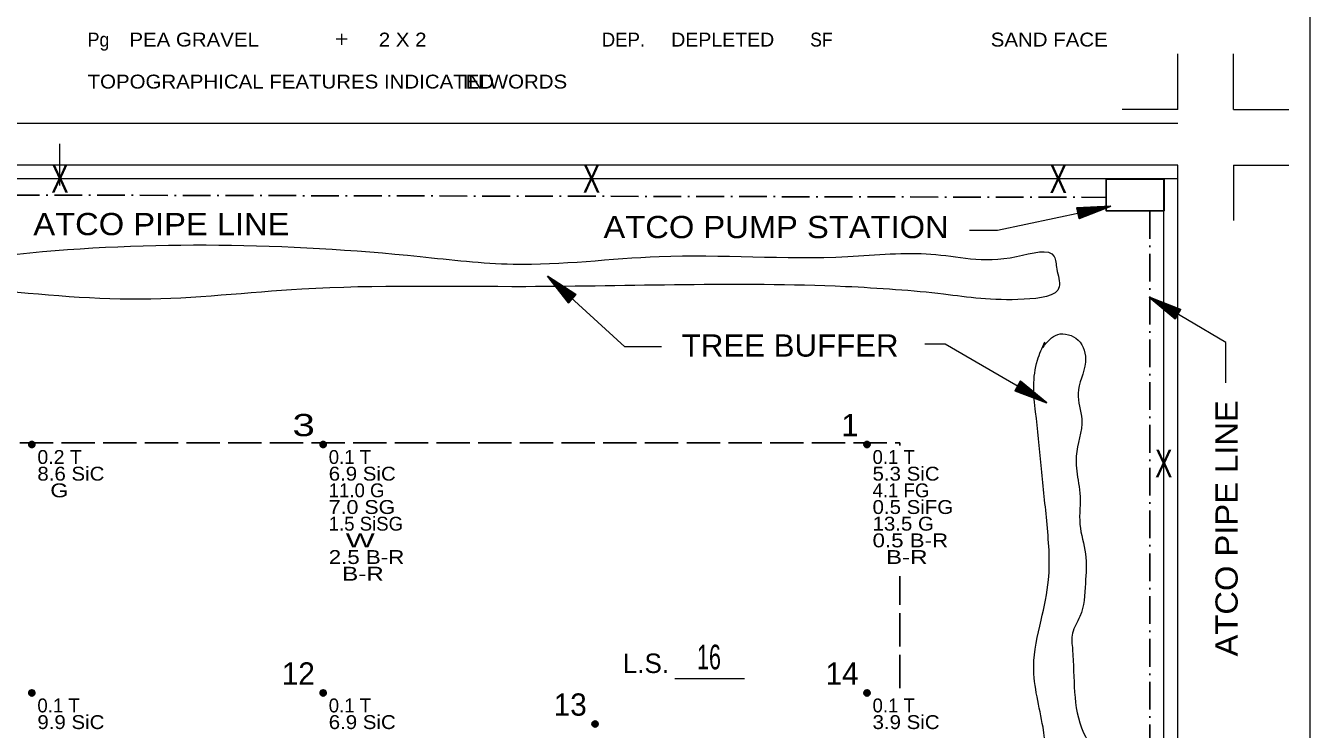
# Model space of a CAD drawing. Extents: x -496 to 480, y -450 to 700.
# Drawn here: x -12.3 to 450, y 199.3 to 452.5 of the extents above; entities that cross this region are included whole.
import ezdxf
from ezdxf.enums import TextEntityAlignment as Align

# ---------------------------------------------------------------- set-up
doc = ezdxf.new("R2010")
doc.units = 0
doc.header["$LTSCALE"] = 2
doc.linetypes.add('DOT_DASHED', pattern=[7.7, 5, -1.2, 0.3, -1.2])
doc.linetypes.add('LONG_DASHED', pattern=[7.5, 6, -1.5])
for name, color, linetype, lineweight in [('1', 7, 'Continuous', 13), ('2', 7, 'Continuous', 35), ('3', 7, 'Continuous', 13), ('4', 7, 'Continuous', 25)]:
    doc.layers.add(name, color=color, linetype=linetype, lineweight=lineweight)

msp = doc.modelspace()

# ---------------------------------------------------------------- linework, layer by layer
at = {"layer": '1'}
for p, q in [((101.291, 449.597), (101.291, 445.597)), ((103.353, 447.618), (99.353, 447.618)), ((402.281, 422.339), (402.281, 442.339)), ((422.281, 422.339), (422.281, 442.339)), ((402.281, 422.339), (382.281, 422.339)), ((422.281, 422.339), (442.281, 422.339)), ((-0.017, 394.973), (-0.017, 409.973)), ((402.281, 402.339), (-402.391, 402.339)), ((402.281, -245.555), (402.281, 402.339)), ((422.281, 402.339), (442.281, 402.339)), ((422.281, 402.339), (422.281, 382.339)), ((221.34, 217.545), (246.34, 217.545))]:
    msp.add_line(p, q, dxfattribs=at)
msp.add_lwpolyline([(449.983, -450.027), (449.983, 399.973), (449.983, 699.973), (-450.017, 699.973), (-450.017, 49.973), (-450.017, -450.027)], dxfattribs=at)
at = {"layer": '2', "linetype": 'LONG_DASHED', "lineweight": 25}
for p, q in [((-74.459, 302.339), (302.281, 302.339)), ((302.281, 301.455), (302.281, 302.339)), ((302.281, 214.038), (302.281, 254.384))]:
    msp.add_line(p, q, dxfattribs=at)
at = {"layer": '2'}
for centre in [(-10.129, 301.764), (94.721, 301.764), (290.441, 301.764), (-10.129, 212.364), (94.721, 212.364), (94.721, 212.364), (290.441, 212.364), (192.581, 201.189)]:
    msp.add_circle(centre, 1, dxfattribs=at)
for points in [[(-10.14, 302.651), (-9.409, 302.247), (-9.258, 301.398), (-9.943, 300.87), (-10.752, 301.101), (-11.038, 301.859), (-10.791, 302.421), (-10.218, 302.589), (-9.544, 302.095), (-9.561, 301.353), (-10.078, 301.095), (-10.6, 301.264), (-10.825, 301.91), (-10.241, 302.376), (-9.803, 301.842), (-9.842, 301.359), (-10.471, 301.494), (-10.325, 302.129), (-10.033, 301.578)], [(94.71, 302.651), (95.441, 302.247), (95.592, 301.398), (94.907, 300.87), (94.098, 301.101), (93.812, 301.859), (94.059, 302.421), (94.632, 302.589), (95.306, 302.095), (95.289, 301.353), (94.772, 301.095), (94.25, 301.264), (94.025, 301.91), (94.609, 302.376), (95.047, 301.842), (95.008, 301.359), (94.379, 301.494), (94.525, 302.129), (94.817, 301.578)], [(290.43, 302.651), (291.161, 302.247), (291.312, 301.398), (290.627, 300.87), (289.818, 301.101), (289.532, 301.859), (289.779, 302.421), (290.352, 302.589), (291.026, 302.095), (291.009, 301.353), (290.492, 301.095), (289.97, 301.264), (289.745, 301.91), (290.329, 302.376), (290.767, 301.842), (290.728, 301.359), (290.099, 301.494), (290.245, 302.129), (290.537, 301.578)], [(-10.14, 213.251), (-9.409, 212.847), (-9.258, 211.998), (-9.943, 211.47), (-10.752, 211.701), (-11.038, 212.459), (-10.791, 213.021), (-10.218, 213.189), (-9.544, 212.695), (-9.561, 211.953), (-10.078, 211.695), (-10.6, 211.864), (-10.825, 212.51), (-10.241, 212.976), (-9.803, 212.442), (-9.842, 211.959), (-10.471, 212.094), (-10.325, 212.729), (-10.033, 212.178)], [(94.71, 213.251), (95.441, 212.847), (95.592, 211.998), (94.907, 211.47), (94.098, 211.701), (93.812, 212.459), (94.059, 213.021), (94.632, 213.189), (95.306, 212.695), (95.289, 211.953), (94.772, 211.695), (94.25, 211.864), (94.025, 212.51), (94.609, 212.976), (95.047, 212.442), (95.008, 211.959), (94.379, 212.094), (94.525, 212.729), (94.817, 212.178)], [(94.71, 213.251), (95.441, 212.847), (95.592, 211.998), (94.907, 211.47), (94.098, 211.701), (93.812, 212.459), (94.059, 213.021), (94.632, 213.189), (95.306, 212.695), (95.289, 211.953), (94.772, 211.695), (94.25, 211.864), (94.025, 212.51), (94.609, 212.976), (95.047, 212.442), (95.008, 211.959), (94.379, 212.094), (94.525, 212.729), (94.817, 212.178)], [(290.43, 213.251), (291.161, 212.847), (291.312, 211.998), (290.627, 211.47), (289.818, 211.701), (289.532, 212.459), (289.779, 213.021), (290.352, 213.189), (291.026, 212.695), (291.009, 211.953), (290.492, 211.695), (289.97, 211.864), (289.745, 212.51), (290.329, 212.976), (290.767, 212.442), (290.728, 211.959), (290.099, 212.094), (290.245, 212.729), (290.537, 212.178)], [(192.57, 202.076), (193.301, 201.672), (193.452, 200.823), (192.767, 200.295), (191.958, 200.526), (191.672, 201.284), (191.919, 201.846), (192.492, 202.014), (193.166, 201.52), (193.149, 200.778), (192.632, 200.52), (192.11, 200.689), (191.885, 201.335), (192.469, 201.801), (192.907, 201.267), (192.868, 200.784), (192.239, 200.919), (192.385, 201.554), (192.677, 201.003)]]:
    msp.add_spline(points, degree=3, dxfattribs=at)
at = {"layer": '3'}
for p, q in [((402.281, 417.339), (-402.391, 417.339)), ((402.281, 397.339), (-402.391, 397.339)), ((397.281, -246.457), (397.281, 397.339))]:
    msp.add_line(p, q, dxfattribs=at)
at = {"layer": '3', "linetype": 'DOT_DASHED', "lineweight": 25}
for p, q in [((-402.402, 392.339), (376.548, 390.701)), ((392.281, 385.802), (392.281, -246.006))]:
    msp.add_line(p, q, dxfattribs=at)
at = {"layer": '3', "lineweight": 25}
msp.add_lwpolyline([(376.548, 397.28), (397.376, 397.28), (397.376, 385.802), (376.548, 385.802)], close=True, dxfattribs=at)
at = {"layer": '3'}
for points in [[(-407.583, 368.504), (-377.691, 369.409), (-355.045, 369.409), (-344.175, 368.504), (-328.776, 371.218), (-313.377, 372.123), (-278.956, 368.504), (-253.593, 366.695), (-220.983, 368.504), (-195.62, 369.409), (-113.189, 371.218), (-62.463, 366.695), (-15.36, 370.314), (129.573, 369.409), (163.088, 366.695), (215.626, 369.409), (283.563, 369.409), (313.456, 370.314), (344.254, 369.409), (357.841, 369.409), (358.747, 364.885), (359.653, 358.552), (346.971, 354.028), (317.985, 355.837), (282.658, 358.552), (167.617, 358.552), (86.999, 357.647), (29.026, 354.028), (-29.853, 357.647), (-94.167, 358.552), (-118.624, 356.742), (-177.503, 359.456), (-248.158, 354.932), (-325.153, 358.552), (-355.951, 354.932), (-383.126, 358.552), (-389.467, 354.932), (-393.996, 342.265), (-393.09, 244.549), (-392.184, 178.5), (-393.996, 113.356), (-393.996, 88.927), (-393.09, 59.974), (-392.184, 33.736), (-397.619, 15.64), (-404.866, 15.64), (-411.207, 31.021), (-407.583, 90.737), (-410.301, 145.024), (-408.489, 188.453), (-408.489, 262.645), (-411.207, 278.931), (-407.583, 312.408), (-409.395, 347.694), (-409.395, 353.123), (-415.736, 357.647)], [(353.782, 336.707), (359.096, 341.351), (366.402, 339.361), (369.059, 331.4), (366.402, 320.121), (367.731, 310.833), (365.738, 297.564), (366.402, 288.94), (367.066, 284.296), (367.066, 273.017), (369.059, 262.402), (369.059, 251.787), (367.066, 239.846), (364.41, 233.875), (364.41, 227.904), (368.395, 198.049), (373.044, 186.771), (371.052, 177.483), (364.41, 148.955), (366.402, 133.696), (368.395, 121.091), (368.395, 112.466), (367.066, 99.861), (367.066, 72.66), (369.723, 64.699), (369.723, 49.44), (369.059, 40.815), (364.41, 24.893), (366.402, 3.663), (367.066, -2.971), (369.059, -10.932), (370.387, -17.567), (370.387, -25.528), (367.731, -28.845), (363.745, -29.509), (359.096, -25.528), (353.782, -9.606), (353.782, 1.673), (354.447, 22.239), (357.103, 35.508), (356.439, 57.401), (353.118, 69.343), (353.118, 100.524), (353.118, 123.081), (351.79, 140.331), (355.775, 152.272), (355.111, 170.185), (355.111, 184.117), (353.782, 200.04), (350.461, 221.933), (353.118, 238.519), (355.775, 253.114), (355.111, 274.344), (353.118, 294.247), (351.125, 313.487), (350.461, 322.775), (351.79, 332.063), (354.447, 338.697)]]:
    msp.add_spline(points, degree=3, dxfattribs=at)
at = {"layer": '4', "lineweight": 13}
for p, q in [((337.44, 378.889), (378.151, 387.481)), ((327.385, 378.889), (337.44, 378.889))]:
    msp.add_line(p, q, dxfattribs=at)
at = {"layer": '4'}
for points in [[(378.151, 387.481), (365.997, 386.96), (366.823, 383.046)], [(175.463, 362.311), (182.973, 352.74), (185.671, 355.693)], [(391.967, 354.757), (401.291, 346.942), (403.321, 350.388)], [(355.111, 316.804), (345.741, 324.563), (343.731, 321.104)]]:
    msp.add_lwpolyline(points, close=True, dxfattribs=at)
for points in [[(366.117, 386.865), (377.589, 387.363), (366.948, 383.241), (366.196, 386.704), (376.869, 387.211), (367.103, 383.448), (366.394, 386.592), (376.107, 387.051), (367.248, 383.702), (366.566, 386.408), (375.237, 386.888), (367.442, 383.941), (366.824, 386.24), (374.194, 386.692), (367.579, 384.235), (367.088, 386.03), (373.071, 386.476), (367.786, 384.611), (367.391, 385.853), (371.829, 386.28), (368.07, 384.936), (367.762, 385.666), (370.374, 385.952), (368.375, 385.374)], [(182.981, 352.893), (175.886, 361.923), (185.44, 355.681), (183.065, 353.051), (176.43, 361.426), (185.181, 355.686), (183.041, 353.278), (177.005, 360.901), (184.891, 355.656), (183.09, 353.524), (177.644, 360.289), (184.583, 355.674), (183.076, 353.832), (178.411, 359.556), (184.264, 355.614), (183.092, 354.169), (179.242, 358.769), (183.839, 355.563), (183.06, 354.518), (180.125, 357.874), (183.409, 355.604), (182.996, 354.928), (181.24, 356.884), (182.875, 355.597)], [(401.266, 347.094), (392.461, 354.465), (403.098, 350.329), (401.317, 347.266), (393.096, 354.091), (402.843, 350.281), (401.246, 347.482), (393.766, 353.696), (402.565, 350.192), (401.243, 347.734), (394.518, 353.229), (402.26, 350.145), (401.166, 348.032), (395.42, 352.67), (401.961, 350.021), (401.112, 348.365), (396.395, 352.072), (401.555, 349.883), (401.009, 348.7), (397.444, 351.378), (401.126, 349.835), (400.861, 349.088), (398.74, 350.639), (400.605, 349.717)], [(345.766, 324.411), (354.615, 317.093), (343.954, 321.164), (345.716, 324.239), (353.978, 317.463), (344.208, 321.215), (345.789, 324.023), (353.305, 317.854), (344.486, 321.306), (345.793, 323.771), (352.551, 318.317), (344.79, 321.354), (345.872, 323.473), (351.645, 318.87), (345.089, 321.48), (345.928, 323.141), (350.667, 319.463), (345.494, 321.62), (346.033, 322.806), (349.614, 320.15), (345.922, 321.671), (346.183, 322.419), (348.314, 320.881), (346.443, 321.792)]]:
    msp.add_lwpolyline(points, dxfattribs=at)
at = {"layer": '4', "lineweight": 13}
for points in [[(216.467, 336.875), (203.302, 336.875), (175.463, 362.311)], [(419.592, 323.988), (419.592, 338.479), (391.967, 354.757)], [(311.273, 338.034), (318.58, 338.034), (355.111, 316.804)]]:
    msp.add_lwpolyline(points, dxfattribs=at)

# ---------------------------------------------------------------- texts
at = {"layer": '1'}
for s, width, p in [('Pg', 0.95, (9.983, 444.973)), ('PEA GRAVEL', 1.1, (24.983, 444.973)), ('   2 X 2', 1.1, (108.608, 444.973)), ('DEPLETED', 1.05, (219.983, 444.973)), ('SF', 0.95, (269.983, 444.973)), ('SAND FACE', 1.1, (334.983, 444.973)), ('TOPOGRAPHICAL FEATURES INDICATED', 1.1, (9.942, 429.855)), ('IN WORDS', 1.1, (144.942, 429.855))]:
    msp.add_text(s, height=5, dxfattribs=dict(at, width=width)).set_placement(p)
msp.add_text('DEP.', height=5, dxfattribs=at).set_placement((194.983, 444.973))
msp.add_text('L.S.', height=7, dxfattribs=at).set_placement((210.878, 219.534), align=Align.CENTER)
at = {"layer": '1', "width": 0.65}
msp.add_text('16', height=8.89, dxfattribs=at).set_placement((233.578, 220.854), align=Align.CENTER)
at = {"layer": '2'}
for s, width, p in [('  3', 1.35, (91.721, 304.764)), ('  1', 1.05, (287.441, 304.764))]:
    msp.add_text(s, height=8, dxfattribs=dict(at, width=width)).set_placement(p, align=Align.RIGHT)
for s, width, p in [('0.2 T      ', 1.05, (-8.129, 294.764)), ('8.6 SiC    ', 1.1, (-8.129, 288.764)), ('6.9 SiC    ', 1.1, (96.721, 288.764)), ('5.3 SiC    ', 1.1, (292.441, 288.764)), ('  G        ', 1.25, (-8.129, 282.764)), ('0.5 SiFG   ', 1.1, (292.441, 276.764)), ('7.0 SG     ', 1.15, (96.721, 276.764)), ('13.5 G     ', 1.1, (292.441, 270.764)), ('  W        ', 1.65, (96.721, 264.764)), ('0.5 B-R    ', 1.2, (292.441, 264.764)), ('2.5 B-R    ', 1.2, (96.721, 258.764)), ('  B-R      ', 1.3, (292.441, 258.764)), ('  B-R      ', 1.3, (96.721, 252.764)), ('9.9 SiC    ', 1.1, (-8.129, 199.364)), ('6.9 SiC    ', 1.1, (96.721, 199.364)), ('3.9 SiC    ', 1.1, (292.441, 199.364))]:
    msp.add_text(s, height=5, dxfattribs=dict(at, width=width)).set_placement(p)
for s, p in [('0.1 T      ', (96.721, 294.764)), ('0.1 T      ', (292.441, 294.764)), ('11.0 G     ', (96.721, 282.764)), ('4.1 FG     ', (292.441, 282.764)), ('1.5 SiSG   ', (96.721, 270.764)), ('0.1 T      ', (-8.129, 205.364)), ('0.1 T      ', (96.721, 205.364)), ('0.1 T      ', (292.441, 205.364))]:
    msp.add_text(s, height=5, dxfattribs=at).set_placement(p)
for s, p in [(' 12', (91.721, 215.364)), (' 14', (287.441, 215.364)), (' 13', (189.581, 204.189))]:
    msp.add_text(s, height=8, dxfattribs=at).set_placement(p, align=Align.RIGHT)
at = {"layer": '3', "width": 0.7}
for p in [(-0.026, 392.374), (191.293, 392.352), (359.277, 392.222), (397.243, 289.892)]:
    msp.add_text('X', height=10, dxfattribs=at).set_placement(p, align=Align.CENTER)
at = {"layer": '4'}
for s, width, p in [('ATCO PIPE LINE', 1.1, (36.515, 377.091)), ('ATCO PUMP STATION', 1.1, (257.719, 376.02)), ('TREE BUFFER', 1.05, (262.786, 333.39))]:
    msp.add_text(s, height=8, dxfattribs=dict(at, width=width)).set_placement(p, align=Align.CENTER)
at = {"layer": '4', "width": 1.1}
msp.add_text('ATCO PIPE LINE', height=8, rotation=90, dxfattribs=at).set_placement((423.845, 271.6), align=Align.CENTER)

doc.saveas('drawing.dxf')
